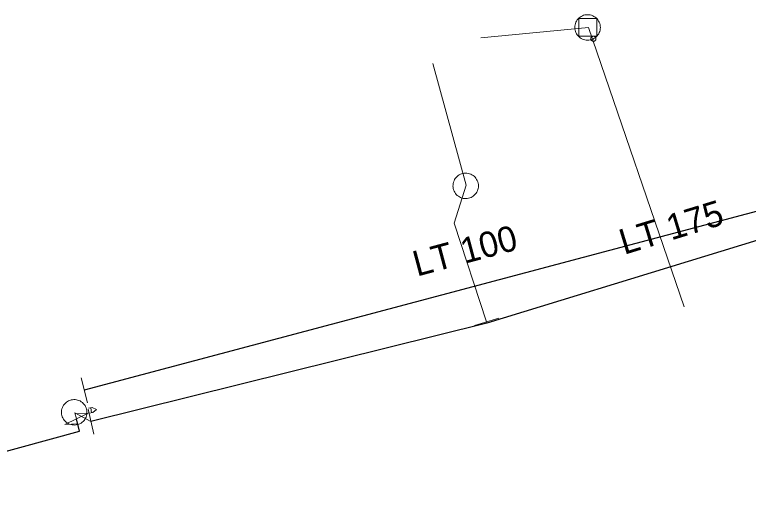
# Model space of a CAD drawing. Extents: x -690254 to -689100, y -975264 to -974703.
# Drawn here: x -690153.75 to -690124.96, y -975179.32 to -975160.4 of the extents above; entities that cross this region are included whole.
import ezdxf

# ---------------------------------------------------------------- set-up
doc = ezdxf.new("R2010")
doc.units = 0
doc.header["$LTSCALE"] = 0.4
doc.header["$PDMODE"] = 32
doc.header["$PDSIZE"] = 0.2
for name, color, linetype, lineweight in [('1', 7, 'Continuous', 13), ('11', 7, 'Continuous', 13), ('13', 7, 'Continuous', 13), ('14', 7, 'Continuous', 13), ('17', 7, 'Continuous', 25), ('22', 7, 'Continuous', 13), ('23', 7, 'Continuous', 13), ('34', 7, 'Continuous', 13), ('47', 7, 'Continuous', 13)]:
    doc.layers.add(name, color=color, linetype=linetype, lineweight=lineweight)

msp = doc.modelspace()

# ---------------------------------------------------------------- linework, layer by layer
at = {"layer": '11'}
for p, q in [((-690135.46, -975161.304), (-690131.239, -975160.91)), ((-690131.239, -975160.91), (-690127.48, -975171.85))]:
    msp.add_line(p, q, dxfattribs=at)
at = {"layer": '13'}
msp.add_lwpolyline([(-690135.235, -975172.447), (-690136.51, -975168.579), (-690136.03, -975167.09), (-690137.344, -975162.311)], dxfattribs=at)
at = {"layer": '14'}
for p, q in [((-690135.219, -975172.5), (-690135.235, -975172.447)), ((-690151.331, -975176.243), (-690151.39, -975176.01)), ((-690150.759, -975176.356), (-690151.39, -975176.01))]:
    msp.add_line(p, q, dxfattribs=at)
at = {"layer": '17'}
for points in [[(-690118.142, -975167.265), (-690118.454, -975166.466), (-690151.024, -975175.128)], [(-690118.142, -975167.265), (-690135.219, -975172.5), (-690150.759, -975176.356)], [(-690160.831, -975179.322), (-690156.055, -975178.048), (-690151.204, -975176.728), (-690151.331, -975176.243)]]:
    msp.add_lwpolyline(points, dxfattribs=at)
at = {"layer": '22'}
for points in [[(-690130.769, -975160.901), (-690130.772, -975160.849), (-690130.781, -975160.796), (-690130.794, -975160.746), (-690130.813, -975160.697), (-690130.837, -975160.651), (-690130.867, -975160.606), (-690130.899, -975160.566), (-690130.936, -975160.53), (-690130.975, -975160.496), (-690131.019, -975160.467), (-690131.068, -975160.443), (-690131.115, -975160.426), (-690131.166, -975160.411), (-690131.218, -975160.403), (-690131.269, -975160.402), (-690131.321, -975160.404), (-690131.375, -975160.413), (-690131.426, -975160.426), (-690131.473, -975160.444), (-690131.519, -975160.469), (-690131.563, -975160.498), (-690131.605, -975160.53), (-690131.642, -975160.568), (-690131.674, -975160.607), (-690131.703, -975160.651), (-690131.727, -975160.699), (-690131.745, -975160.747), (-690131.759, -975160.797), (-690131.766, -975160.85), (-690131.769, -975160.901), (-690131.766, -975160.953), (-690131.757, -975161.006), (-690131.745, -975161.057), (-690131.725, -975161.105), (-690131.701, -975161.151), (-690131.674, -975161.196), (-690131.641, -975161.236), (-690131.603, -975161.273), (-690131.563, -975161.306), (-690131.519, -975161.335), (-690131.472, -975161.358), (-690131.424, -975161.377), (-690131.372, -975161.391), (-690131.321, -975161.398), (-690131.269, -975161.401), (-690131.218, -975161.398), (-690131.164, -975161.389), (-690131.115, -975161.377), (-690131.066, -975161.357), (-690131.019, -975161.333), (-690130.975, -975161.305), (-690130.934, -975161.273), (-690130.899, -975161.235), (-690130.865, -975161.195), (-690130.835, -975161.151), (-690130.811, -975161.103), (-690130.794, -975161.056), (-690130.779, -975161.005), (-690130.772, -975160.952)], [(-690131.62, -975160.551), (-690130.911, -975160.55), (-690130.911, -975161.244), (-690131.62, -975161.244)]]:
    msp.add_lwpolyline(points, close=True, dxfattribs=at)
msp.add_point((-690131.044, -975161.349), dxfattribs=at)
at = {"layer": '23'}
msp.add_line((-690150.736, -975176.008), (-690150.763, -975175.813), dxfattribs=at)
for points in [[(-690135.553, -975167.107), (-690135.556, -975167.054), (-690135.565, -975167.002), (-690135.58, -975166.953), (-690135.599, -975166.904), (-690135.623, -975166.858), (-690135.653, -975166.814), (-690135.686, -975166.774), (-690135.723, -975166.738), (-690135.764, -975166.705), (-690135.808, -975166.677), (-690135.855, -975166.653), (-690135.905, -975166.635), (-690135.955, -975166.622), (-690136.006, -975166.615), (-690136.058, -975166.612), (-690136.112, -975166.616), (-690136.162, -975166.624), (-690136.214, -975166.639), (-690136.261, -975166.657), (-690136.308, -975166.681), (-690136.352, -975166.712), (-690136.392, -975166.745), (-690136.429, -975166.783), (-690136.462, -975166.823), (-690136.489, -975166.867), (-690136.512, -975166.915), (-690136.53, -975166.963), (-690136.543, -975167.014), (-690136.55, -975167.066), (-690136.553, -975167.118), (-690136.55, -975167.17), (-690136.541, -975167.222), (-690136.527, -975167.273), (-690136.508, -975167.321), (-690136.483, -975167.366), (-690136.454, -975167.41), (-690136.421, -975167.451), (-690136.383, -975167.488), (-690136.342, -975167.52)], [(-690136.342, -975167.52), (-690136.299, -975167.548), (-690136.251, -975167.571), (-690136.203, -975167.59), (-690136.151, -975167.602), (-690136.1, -975167.609), (-690136.048, -975167.612), (-690135.996, -975167.608), (-690135.944, -975167.6), (-690135.893, -975167.586), (-690135.845, -975167.566), (-690135.798, -975167.542), (-690135.755, -975167.514), (-690135.715, -975167.479), (-690135.678, -975167.443), (-690135.646, -975167.402), (-690135.617, -975167.357), (-690135.594, -975167.31), (-690135.576, -975167.261), (-690135.564, -975167.21), (-690135.556, -975167.159), (-690135.553, -975167.107), (-690135.556, -975167.054), (-690135.565, -975167.002), (-690135.58, -975166.953), (-690135.599, -975166.904), (-690135.623, -975166.858), (-690135.653, -975166.814), (-690135.686, -975166.774), (-690135.723, -975166.738), (-690135.764, -975166.705), (-690135.808, -975166.677), (-690135.855, -975166.653), (-690135.905, -975166.635), (-690135.955, -975166.622), (-690136.006, -975166.615), (-690136.058, -975166.612), (-690136.112, -975166.616), (-690136.162, -975166.624), (-690136.214, -975166.639)], [(-690136.214, -975166.639), (-690136.261, -975166.657), (-690136.308, -975166.681), (-690136.352, -975166.712), (-690136.392, -975166.745), (-690136.429, -975166.783), (-690136.462, -975166.823), (-690136.489, -975166.867), (-690136.512, -975166.915), (-690136.53, -975166.963), (-690136.543, -975167.014), (-690136.55, -975167.066), (-690136.553, -975167.118), (-690136.55, -975167.17), (-690136.541, -975167.222), (-690136.527, -975167.273), (-690136.508, -975167.321), (-690136.483, -975167.366), (-690136.454, -975167.41), (-690136.421, -975167.451), (-690136.383, -975167.488), (-690136.342, -975167.52), (-690136.299, -975167.548), (-690136.251, -975167.571), (-690136.203, -975167.59), (-690136.151, -975167.602), (-690136.1, -975167.609), (-690136.048, -975167.612), (-690135.996, -975167.608), (-690135.944, -975167.6), (-690135.893, -975167.586), (-690135.845, -975167.566), (-690135.798, -975167.542), (-690135.755, -975167.514), (-690135.715, -975167.479), (-690135.678, -975167.443), (-690135.646, -975167.402), (-690135.617, -975167.357), (-690135.594, -975167.31), (-690135.576, -975167.261)], [(-690135.576, -975167.261), (-690135.564, -975167.21), (-690135.556, -975167.159), (-690135.553, -975167.107)], [(-690150.968, -975175.767), (-690150.992, -975175.722), (-690151.022, -975175.679), (-690151.059, -975175.64), (-690151.097, -975175.604), (-690151.139, -975175.573), (-690151.184, -975175.546), (-690151.231, -975175.525), (-690151.281, -975175.508), (-690151.331, -975175.497), (-690151.384, -975175.491), (-690151.436, -975175.491), (-690151.488, -975175.495), (-690151.539, -975175.505), (-690151.59, -975175.521), (-690151.638, -975175.542), (-690151.683, -975175.567), (-690151.724, -975175.598), (-690151.764, -975175.632), (-690151.8, -975175.671), (-690151.832, -975175.713), (-690151.858, -975175.758), (-690151.88, -975175.805), (-690151.896, -975175.855), (-690151.909, -975175.905), (-690151.914, -975175.959), (-690151.914, -975176.01), (-690151.91, -975176.062), (-690151.899, -975176.113), (-690151.884, -975176.163), (-690151.863, -975176.212), (-690151.837, -975176.257), (-690151.807, -975176.3), (-690151.773, -975176.339), (-690151.733, -975176.374), (-690151.692, -975176.406), (-690151.648, -975176.432), (-690151.599, -975176.455), (-690151.549, -975176.471), (-690151.498, -975176.482)], [(-690151.343, -975176.485), (-690151.291, -975176.474), (-690151.24, -975176.459), (-690151.194, -975176.437), (-690151.148, -975176.412), (-690151.105, -975176.382), (-690151.066, -975176.346), (-690151.031, -975176.308), (-690151, -975176.266), (-690150.973, -975176.221), (-690150.951, -975176.174), (-690150.933, -975176.124), (-690150.922, -975176.072), (-690150.916, -975176.021), (-690150.916, -975175.969), (-690150.92, -975175.918), (-690150.931, -975175.865), (-690150.946, -975175.816), (-690150.968, -975175.767), (-690150.992, -975175.722), (-690151.022, -975175.679), (-690151.059, -975175.64), (-690151.097, -975175.604), (-690151.139, -975175.573), (-690151.184, -975175.546), (-690151.231, -975175.525), (-690151.281, -975175.508), (-690151.331, -975175.497), (-690151.384, -975175.491), (-690151.436, -975175.491), (-690151.488, -975175.495), (-690151.539, -975175.505), (-690151.59, -975175.521), (-690151.638, -975175.542), (-690151.683, -975175.567), (-690151.724, -975175.598), (-690151.764, -975175.632), (-690151.8, -975175.671), (-690151.832, -975175.713), (-690151.858, -975175.758)], [(-690151.858, -975175.758), (-690151.88, -975175.805), (-690151.896, -975175.855), (-690151.909, -975175.905), (-690151.914, -975175.959), (-690151.914, -975176.01), (-690151.91, -975176.062), (-690151.899, -975176.113), (-690151.884, -975176.163), (-690151.863, -975176.212), (-690151.837, -975176.257), (-690151.807, -975176.3), (-690151.773, -975176.339), (-690151.733, -975176.374), (-690151.692, -975176.406), (-690151.648, -975176.432), (-690151.599, -975176.455), (-690151.549, -975176.471), (-690151.498, -975176.482), (-690151.446, -975176.487), (-690151.395, -975176.489), (-690151.343, -975176.485), (-690151.291, -975176.474), (-690151.24, -975176.459), (-690151.194, -975176.437), (-690151.148, -975176.412), (-690151.105, -975176.382), (-690151.066, -975176.346), (-690151.031, -975176.308), (-690151, -975176.266), (-690150.973, -975176.221), (-690150.951, -975176.174), (-690150.933, -975176.124), (-690150.922, -975176.072), (-690150.916, -975176.021), (-690150.916, -975175.969), (-690150.92, -975175.918), (-690150.931, -975175.865), (-690150.946, -975175.816), (-690150.968, -975175.767)], [(-690150.859, -975175.826), (-690150.711, -975175.806), (-690150.548, -975175.884), (-690150.685, -975176.001), (-690150.832, -975176.021)], [(-690151.498, -975176.482), (-690151.446, -975176.487), (-690151.395, -975176.489), (-690151.343, -975176.485)]]:
    msp.add_lwpolyline(points, dxfattribs=at)
at = {"layer": '34'}
for p, q in [((-690135.713, -975172.593), (-690134.756, -975172.301)), ((-690150.9, -975175.612), (-690151.146, -975174.643)), ((-690150.642, -975176.842), (-690150.874, -975175.869))]:
    msp.add_line(p, q, dxfattribs=at)
at = {"layer": '47'}
msp.add_line((-690151.789, -975176.464), (-690151.28, -975176.437), dxfattribs=at)
msp.add_lwpolyline([(-690151.789, -975176.464), (-690150.872, -975176.021), (-690151.381, -975176.048)], dxfattribs=at)

# ---------------------------------------------------------------- texts
at = {"layer": '1'}
for s, rotation, p in [('LT 175', 17, (-690129.837, -975169.819)), ('LT 100', 15, (-690137.967, -975170.672))]:
    msp.add_text(s, height=1, rotation=rotation, dxfattribs=at).set_placement(p)

doc.saveas('drawing.dxf')
